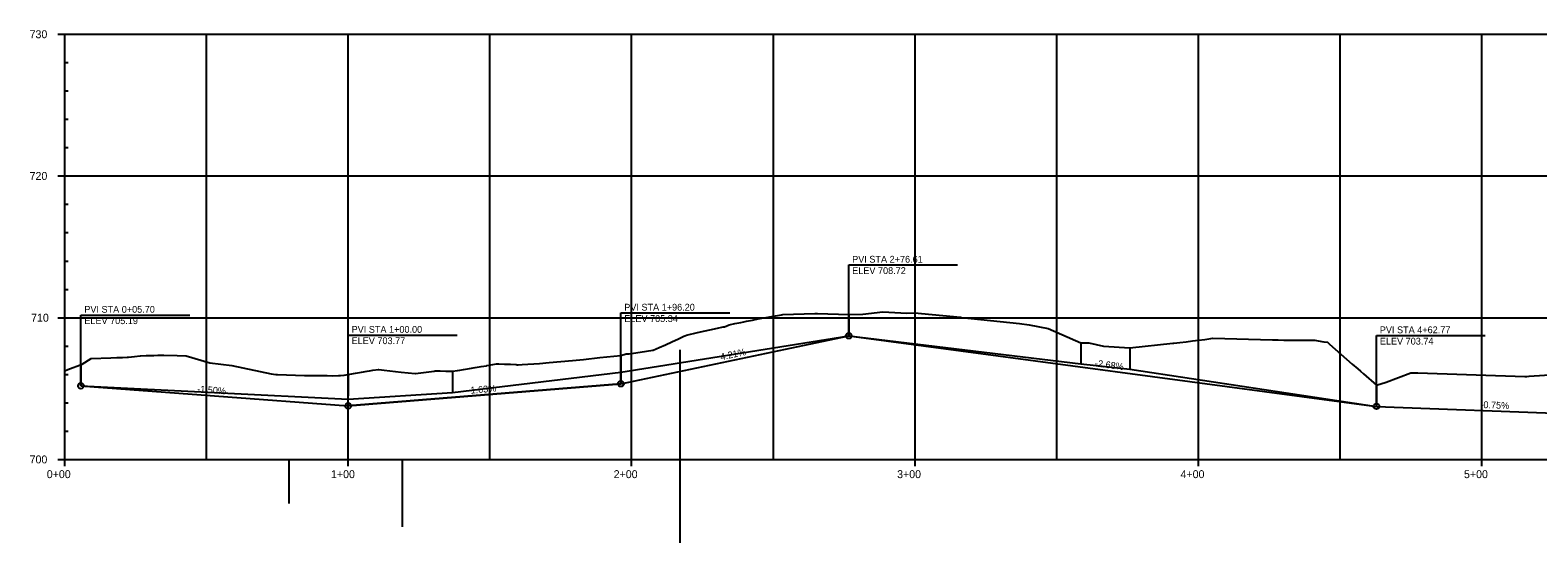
# Model space of a CAD drawing. Extents: x 1487507 to 1489130, y 497211 to 499439.
# Drawn here: x 1487507 to 1488039, y 497226 to 497406 of the extents above; entities that cross this region are included whole.
import ezdxf

# ---------------------------------------------------------------- set-up
doc = ezdxf.new("R2010")
doc.units = 0
doc.layers.add('Default', color=7, linetype='Continuous')

msp = doc.modelspace()

# ---------------------------------------------------------------- linework, layer by layer
at = {"layer": 'Default'}
for p, q in [((1487516.9, 497404.95), (1487521.7, 497404.95)), ((1487516.9, 497404.95), (1487521.7, 497404.95)), ((1487519.3, 497254.95), (1487519.3, 497404.95)), ((1487519.3, 497404.95), (1488519.3, 497404.95)), ((1487519.3, 497404.95), (1488519.3, 497404.95)), ((1487569.3, 497254.95), (1487569.3, 497404.95)), ((1487619.3, 497254.95), (1487619.3, 497404.95)), ((1487669.3, 497254.95), (1487669.3, 497404.95)), ((1487719.3, 497254.95), (1487719.3, 497404.95)), ((1487769.3, 497254.95), (1487769.3, 497404.95)), ((1487819.3, 497254.95), (1487819.3, 497404.95)), ((1487869.3, 497254.95), (1487869.3, 497404.95)), ((1487919.3, 497254.95), (1487919.3, 497404.95)), ((1487969.3, 497254.95), (1487969.3, 497404.95)), ((1488019.3, 497254.95), (1488019.3, 497404.95)), ((1487519.3, 497394.95), (1487520.5, 497394.95)), ((1487519.3, 497384.95), (1487520.5, 497384.95)), ((1487519.3, 497374.95), (1487520.5, 497374.95)), ((1487519.3, 497364.95), (1487520.5, 497364.95)), ((1487516.9, 497354.95), (1487521.7, 497354.95)), ((1487519.3, 497354.95), (1488519.3, 497354.95)), ((1487519.3, 497344.95), (1487520.5, 497344.95)), ((1487519.3, 497334.95), (1487520.5, 497334.95)), ((1487519.3, 497324.95), (1487520.5, 497324.95)), ((1487795.91, 497298.57), (1487795.91, 497323.57)), ((1487795.91, 497323.57), (1487834.31, 497323.57)), ((1487519.3, 497314.95), (1487520.5, 497314.95)), ((1487516.9, 497304.95), (1487521.7, 497304.95)), ((1487519.3, 497304.95), (1488519.3, 497304.95)), ((1487525, 497280.89), (1487525, 497305.89)), ((1487525, 497305.89), (1487563.4, 497305.89)), ((1487715.5, 497281.65), (1487715.5, 497306.65)), ((1487715.5, 497306.65), (1487753.9, 497306.65)), ((1487795.91, 497306.07), (1487795.91, 497298.57)), ((1487619.3, 497273.82), (1487619.3, 497298.82)), ((1487619.3, 497298.82), (1487657.7, 497298.82)), ((1487715.5, 497281.65), (1487795.91, 497298.57)), ((1487715.5, 497281.65), (1487795.91, 497298.57)), ((1487795.91, 497298.57), (1487982.07, 497273.67)), ((1487795.91, 497298.57), (1487982.07, 497273.67)), ((1487982.07, 497273.67), (1487982.07, 497298.67)), ((1487982.07, 497298.67), (1488020.47, 497298.67)), ((1487519.3, 497294.95), (1487520.5, 497294.95)), ((1487736.3, 497293.65), (1487736.3, 497225.52)), ((1487877.82, 497296.13), (1487877.82, 497288.63)), ((1487895.03, 497294.3), (1487895.03, 497286.8)), ((1487525, 497288.39), (1487525, 497280.89)), ((1487715.5, 497291.65), (1487715.5, 497285.77)), ((1487715.5, 497291.65), (1487715.5, 497281.65)), ((1487519.3, 497284.95), (1487520.5, 497284.95)), ((1487619.3, 497284.91), (1487619.3, 497277.41)), ((1487656.06, 497286.04), (1487656.06, 497278.54)), ((1487525, 497280.89), (1487619.3, 497276.18)), ((1487525, 497280.89), (1487619.3, 497273.82)), ((1487525, 497280.89), (1487619.3, 497273.82)), ((1487715.5, 497281.65), (1487619.3, 497273.82)), ((1487619.3, 497273.82), (1487715.5, 497281.65)), ((1487982.07, 497281.17), (1487982.07, 497273.67)), ((1487519.3, 497274.95), (1487520.5, 497274.95)), ((1487982.07, 497273.67), (1488068.3, 497270.44)), ((1487982.07, 497273.67), (1488068.3, 497270.44)), ((1487519.3, 497264.95), (1487520.5, 497264.95)), ((1487519.3, 497252.55), (1487519.3, 497257.35)), ((1487569.3, 497254.95), (1487569.3, 497256.15)), ((1487619.3, 497252.55), (1487619.3, 497257.35)), ((1487669.3, 497254.95), (1487669.3, 497256.15)), ((1487719.3, 497252.55), (1487719.3, 497257.35)), ((1487769.3, 497254.95), (1487769.3, 497256.15)), ((1487819.3, 497252.55), (1487819.3, 497257.35)), ((1487869.3, 497254.95), (1487869.3, 497256.15)), ((1487919.3, 497252.55), (1487919.3, 497257.35)), ((1487969.3, 497254.95), (1487969.3, 497256.15)), ((1488019.3, 497252.55), (1488019.3, 497257.35)), ((1487516.9, 497254.95), (1487521.7, 497254.95)), ((1487519.3, 497254.95), (1488519.3, 497254.95)), ((1487598.3, 497254.95), (1487598.3, 497239.37)), ((1487638.3, 497254.95), (1487638.3, 497231.12))]:
    msp.add_line(p, q, dxfattribs=at)
for points in [[(1487519.3, 497286.21), (1487520.43, 497286.69), (1487525.46, 497288.6), (1487528.59, 497290.53), (1487535.57, 497290.82), (1487537.64, 497290.89), (1487539.71, 497290.94), (1487541.26, 497290.97), (1487541.78, 497291.03), (1487543.85, 497291.25), (1487545.92, 497291.48), (1487546.05, 497291.49), (1487548, 497291.57), (1487550.07, 497291.65), (1487550.78, 497291.67), (1487552.14, 497291.68), (1487554.21, 497291.68), (1487558.94, 497291.67), (1487562.16, 497291.45), (1487570.53, 497288.99), (1487578.24, 497288.13), (1487592.14, 497285.17), (1487593.72, 497284.9), (1487594.33, 497284.93), (1487603.91, 497284.55), (1487605.31, 497284.5), (1487605.91, 497284.5), (1487607.91, 497284.5), (1487609.92, 497284.52), (1487610.51, 497284.54), (1487611.92, 497284.51), (1487613.92, 497284.49), (1487615.92, 497284.5), (1487616.59, 497284.51), (1487617.93, 497284.7), (1487619.93, 497285.01), (1487621.93, 497285.34), (1487623.94, 497285.69), (1487625.94, 497286.08), (1487626.76, 497286.24), (1487627.94, 497286.39), (1487629.94, 497286.66), (1487630.12, 497286.68), (1487631.95, 497286.43), (1487633.95, 497286.18), (1487635.95, 497285.96), (1487637.95, 497285.76), (1487642.94, 497285.31), (1487643.05, 497285.32), (1487649.62, 497286.11), (1487650.03, 497286.16), (1487651.69, 497286.15), (1487653.76, 497286.11), (1487655.83, 497286.05), (1487656.06, 497286.04), (1487657.9, 497286.35), (1487658.65, 497286.47), (1487659.97, 497286.72), (1487662.04, 497287.08), (1487664.11, 497287.42), (1487666.18, 497287.73), (1487668.07, 497287.99), (1487668.25, 497288.03), (1487670.32, 497288.45), (1487671.67, 497288.7), (1487672.39, 497288.68), (1487674.46, 497288.6), (1487676.53, 497288.51), (1487678.6, 497288.39), (1487678.86, 497288.37), (1487679.16, 497288.37), (1487679.29, 497288.36), (1487680.67, 497288.45), (1487686.78, 497288.8), (1487690.15, 497289.16), (1487698.44, 497289.88), (1487701.01, 497290.13), (1487702.27, 497290.21), (1487708.11, 497290.88), (1487715.5, 497291.65), (1487717.31, 497292.23), (1487718.41, 497292.19), (1487722.25, 497292.76), (1487724.5, 497293.11), (1487726.76, 497293.5), (1487726.94, 497293.53), (1487729.01, 497294.4), (1487731.27, 497295.39), (1487733.52, 497296.4), (1487735.78, 497297.45), (1487737.76, 497298.39), (1487738.03, 497298.54), (1487738.6, 497298.84), (1487742.49, 497299.69), (1487749.59, 497301.25), (1487751.64, 497301.69), (1487752.05, 497301.78), (1487753.69, 497302.39), (1487753.75, 497302.42), (1487755.74, 497302.85), (1487757.79, 497303.26), (1487758.88, 497303.47), (1487759.84, 497303.68), (1487761.89, 497304.1), (1487763.94, 497304.5), (1487765.99, 497304.87), (1487768.04, 497305.22), (1487768.71, 497305.33), (1487770.09, 497305.59), (1487772.14, 497305.96), (1487772.63, 497306.05), (1487783.95, 497306.38), (1487784.9, 497306.4), (1487795.91, 497306.07), (1487800.82, 497306.21), (1487807.91, 497306.96), (1487816.38, 497306.57), (1487819.05, 497306.69), (1487835.36, 497305.09), (1487835.69, 497305.06), (1487839.04, 497304.66), (1487856.1, 497302.87), (1487859.57, 497302.4), (1487866.23, 497301.16), (1487877.82, 497296.13), (1487880.56, 497296.06), (1487885.8, 497294.95), (1487895.03, 497294.3), (1487910.27, 497295.92), (1487910.55, 497295.95), (1487912.74, 497296.21), (1487914.93, 497296.47), (1487917.12, 497296.73), (1487919.31, 497297.01), (1487921.5, 497297.3), (1487923.69, 497297.6), (1487924.35, 497297.69), (1487945.43, 497297.16), (1487947.43, 497297.12), (1487949.43, 497297.07), (1487951.44, 497297.04), (1487953.44, 497297.01), (1487955.45, 497296.99), (1487957.45, 497296.98), (1487959.46, 497296.97), (1487960.38, 497296.97), (1487961.46, 497296.8), (1487963.47, 497296.49), (1487964.76, 497296.31), (1487965.47, 497295.66), (1487967.48, 497293.87), (1487969.48, 497292.09), (1487971.49, 497290.34), (1487973.49, 497288.61), (1487975.5, 497286.9), (1487976.41, 497286.14), (1487977.5, 497285.17), (1487982.07, 497281.17), (1487985.51, 497282.24), (1487994.19, 497285.55), (1487996.63, 497285.45), (1488034.45, 497284.25), (1488035.09, 497284.18), (1488035.99, 497284.34), (1488070.32, 497286.6)], [(1487619.3, 497276.18), (1487656.06, 497278.54), (1487715.5, 497285.77), (1487795.91, 497298.57)], [(1487795.91, 497298.57), (1487877.82, 497288.63), (1487895.03, 497286.8), (1487982.07, 497273.67)]]:
    msp.add_lwpolyline(points, dxfattribs=at)
for centre in [(1487795.91, 497298.57), (1487715.5, 497281.65), (1487525, 497280.89), (1487619.3, 497273.82), (1487982.07, 497273.67)]:
    msp.add_circle(centre, 1, dxfattribs=at)

# ---------------------------------------------------------------- texts
for s, height, p in [('730', 2.8, (1487506.9, 497403.55)), ('730', 2.8, (1487506.9, 497403.55)), ('720', 2.8, (1487506.9, 497353.55)), ('PVI STA 2+76.61', 2.4, (1487797.11, 497324.37)), ('ELEV 708.72', 2.4, (1487797.11, 497320.37)), ('PVI STA 0+05.70', 2.4, (1487526.2, 497306.69)), ('PVI STA 1+96.20', 2.4, (1487716.7, 497307.45)), ('710', 2.8, (1487507.43, 497303.55)), ('ELEV 705.19', 2.4, (1487526.2, 497302.69)), ('ELEV 705.34', 2.4, (1487716.7, 497303.45)), ('PVI STA 1+00.00', 2.4, (1487620.5, 497299.62)), ('PVI STA 4+62.77', 2.4, (1487983.27, 497299.47)), ('ELEV 703.77', 2.4, (1487620.5, 497295.62)), ('ELEV 703.74', 2.4, (1487983.27, 497295.47)), ('700', 2.8, (1487506.9, 497253.55)), ('0+00', 2.8, (1487512.96, 497248.35)), ('1+00', 2.8, (1487613.23, 497248.35)), ('2+00', 2.8, (1487712.96, 497248.35)), ('3+00', 2.8, (1487812.96, 497248.35)), ('4+00', 2.8, (1487912.96, 497248.35)), ('5+00', 2.8, (1488012.96, 497248.35))]:
    msp.add_text(s, height=height, dxfattribs=at).set_placement(p)
for s, rotation, p in [('4.21%', 11.8811, (1487750.84, 497289.91)), ('-2.68%', 352.3814, (1487882.64, 497287.78)), ('-1.50%', 355.7108, (1487565.94, 497278.62)), ('1.63%', 4.6564, (1487662.55, 497278.14)), ('-0.75%', 357.8524, (1488018.7, 497273.1))]:
    msp.add_text(s, height=2.4, rotation=rotation, dxfattribs=at).set_placement(p)

doc.saveas('drawing.dxf')
